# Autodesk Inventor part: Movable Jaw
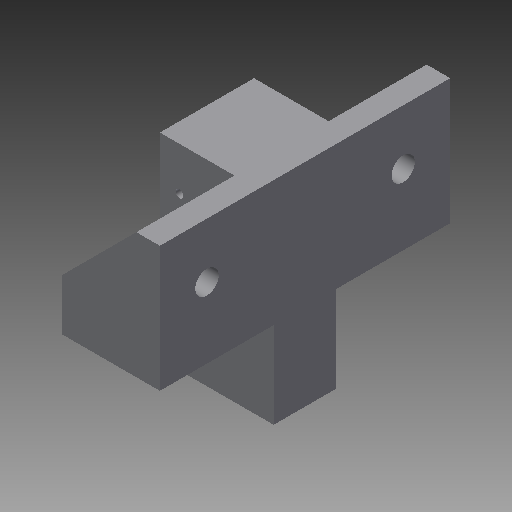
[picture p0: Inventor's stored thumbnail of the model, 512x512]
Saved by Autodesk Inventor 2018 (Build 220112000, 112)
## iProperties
Shininess: 77.0
Length Units: 11269
Angle Units: 11279
Time Units: 11290
Mass Units: 11283
Length Display Precision: 3
Angle Display Precision: 2
Created: 2002-02
Part Number: Movable Jaw
Document SubType Name: Modeling
Designer: ***
Density: 1 g/cm^3
Material: Generic
Appearance: Default
Density: 0.0
Volumn: 0.0
Area: 0.0
PropertySet Name: Model Information
Control State: 0
Master: False
Checked Out: False
Author: ***
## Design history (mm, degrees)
sketch "Sketch2"
  geometry: L1 (2.39, 41.509)-(2.39, 9.509); L2 (2.39, 9.509)-(-22.61, 9.509); L3 (-22.61, 9.509)-(-22.61, 22.509); L4 (-22.61, 22.509)-(-3.61, 41.509); L5 (-3.61, 41.509)-(2.39, 41.509)
  constraints: 10 end point, 2 parallel, 1 perpendicular, 1 vertical
  dimensions: "d0" = 25 distance of L1.end L2.end; "d2" = 13 distance of L2.end L3.end; "d3" = 32 distance between parallel lines of L5 L2; "d4" = 6 distance of L4.end L1.start
extrude "Extrusion1" new body sketch "Sketch2" stored distance "d5" = 74; taper "d6" = 0 deg
sketch "Sketch3"
  geometry: L1 (-19, 25)-(11, 25); L2 (11, 25)-(11, 49); L3 (11, 49)-(-19, 49); L4 (-19, 49)-(-19, 25); L5 (0, 0)-(13, 0) reference; L6 (-19, 74)-(-19, 0) reference; L7 (11.924, 29)-(35, 29); L8 (35, 29)-(35, 45); L9 (35, 45)-(11.924, 45); L10 (11.924, 45)-(11.924, 29); L11 (13, 74)-(13, 0) reference
  constraints: 16 end point, 4 parallel, 2 horizontal, 2 perpendicular, 1 collinear
  dimensions: "d7" = 24 distance of L3.end L1.start; "d8" = 30 distance of L1.start L1.end; "d9" = 25 distance between parallel lines of L5 L1; "d10" = 16 distance of L7.end L8.end; "d11" = 4 distance between parallel lines of L3 L9; "d12" = 22 distance between parallel lines of L11 L8
extrude "Extrusion2" join sketch "Sketch3" distance "d13" = 25; taper "d14" = 0 deg
sketch "Sketch4"
  geometry: L1 (-19, -25)-(-19, -49) reference; L2 (-19, -49)-(0, -49) reference; 1 further point
  dimensions: "d15" = 11 distance from line of L1 point (-8, -37); "d16" = 12 distance from line of L2 point (-8, -37)
hole "Hole1" sketch "Sketch4" at (-8, -37) diameter "d17" = 10; stored, may be unused: countersink angle "d21" = 82 deg, drill point angle "d23" = 0 deg; dims "d18" = 6, "d19" = 4, "d20" = 2, "d22" = 13
sketch "Sketch5"
  geometry: L1 (-19, -49)-(-19, -74) reference; L2 (0, -74)-(13, -74) reference; 1 further point
  dimensions: "d24" = 14 distance from line of L1 point (-5, -62); "d25" = 12 distance from line of L2 point (-5, -62)
hole "Hole2" sketch "Sketch5" at (-5, -62) diameter "d26" = 6; stored, may be unused: countersink angle "d30" = 82 deg, drill point angle "d32" = 0 deg; dims "d27" = 6, "d28" = 8, "d29" = 10, "d31" = 13
mirror "Mirror1"
sketch "Sketch6"
  geometry: L1 (0, 19)-(0, 0) reference; 1 further point
  dimensions: "d33" = 5 distance from line of L1 point (-5, 8); "d34" = 11 vertical distance of L1.start point (-5, 8)
hole "Hole3" sketch "Sketch6" at (-5, 8) diameter "d35" = 2; stored, may be unused: countersink angle "d39" = 82 deg, drill point angle "d41" = 0 deg; dims "d36" = 6, "d37" = 8, "d38" = 10, "d40" = 13
body "Solid1"
